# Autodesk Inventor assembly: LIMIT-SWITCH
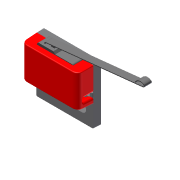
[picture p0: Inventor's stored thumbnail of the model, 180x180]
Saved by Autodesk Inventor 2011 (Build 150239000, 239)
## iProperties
Created: 2007-12
Part Number: LIMIT-SWITCH
Document SubType Name: Assembly
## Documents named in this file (4)
- C:\Data Folder\VEX 2011\Inventor Datasets\Unit 6\Components\LIMIT-SWITCH.iam
- C:\Data Folder\VEX 2011\Inventor Datasets\Unit 6\Components\LIMIT-SWITCH-MICROSWITCH.ipt
- C:\Data Folder\VEX 2011\Inventor Datasets\Unit 6\Components\LIMIT-SWITCH-BOTTOM.ipt
- C:\Data Folder\VEX 2011\Inventor Datasets\Unit 6\Components\LIMIT-SWITCH-TOP.ipt
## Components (3 placed, 3 different names)
1. LIMIT-SWITCH-MICROSWITCH:1 — Mate:5, Mate:6, Mate:7
2. LIMIT-SWITCH-BOTTOM:1 — Mate:1, Mate:2, Insert:1, Insert:2, Mate:5, Mate:6, Mate:7
3. LIMIT-SWITCH-TOP:1 — Insert:1, Insert:2
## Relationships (7: Mate 5, Insert 2)
- Mate:1: LIMIT-SWITCH-BOTTOM:1
- Mate:2: LIMIT-SWITCH-BOTTOM:1
- Insert:1: LIMIT-SWITCH-BOTTOM:1 ↔ LIMIT-SWITCH-TOP:1
- Insert:2: LIMIT-SWITCH-BOTTOM:1 ↔ LIMIT-SWITCH-TOP:1
- Mate:5: LIMIT-SWITCH-MICROSWITCH:1 ↔ LIMIT-SWITCH-BOTTOM:1
- Mate:6: LIMIT-SWITCH-MICROSWITCH:1 ↔ LIMIT-SWITCH-BOTTOM:1
- Mate:7: LIMIT-SWITCH-MICROSWITCH:1 ↔ LIMIT-SWITCH-BOTTOM:1
